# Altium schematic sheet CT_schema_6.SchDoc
size 274 x 160 mm
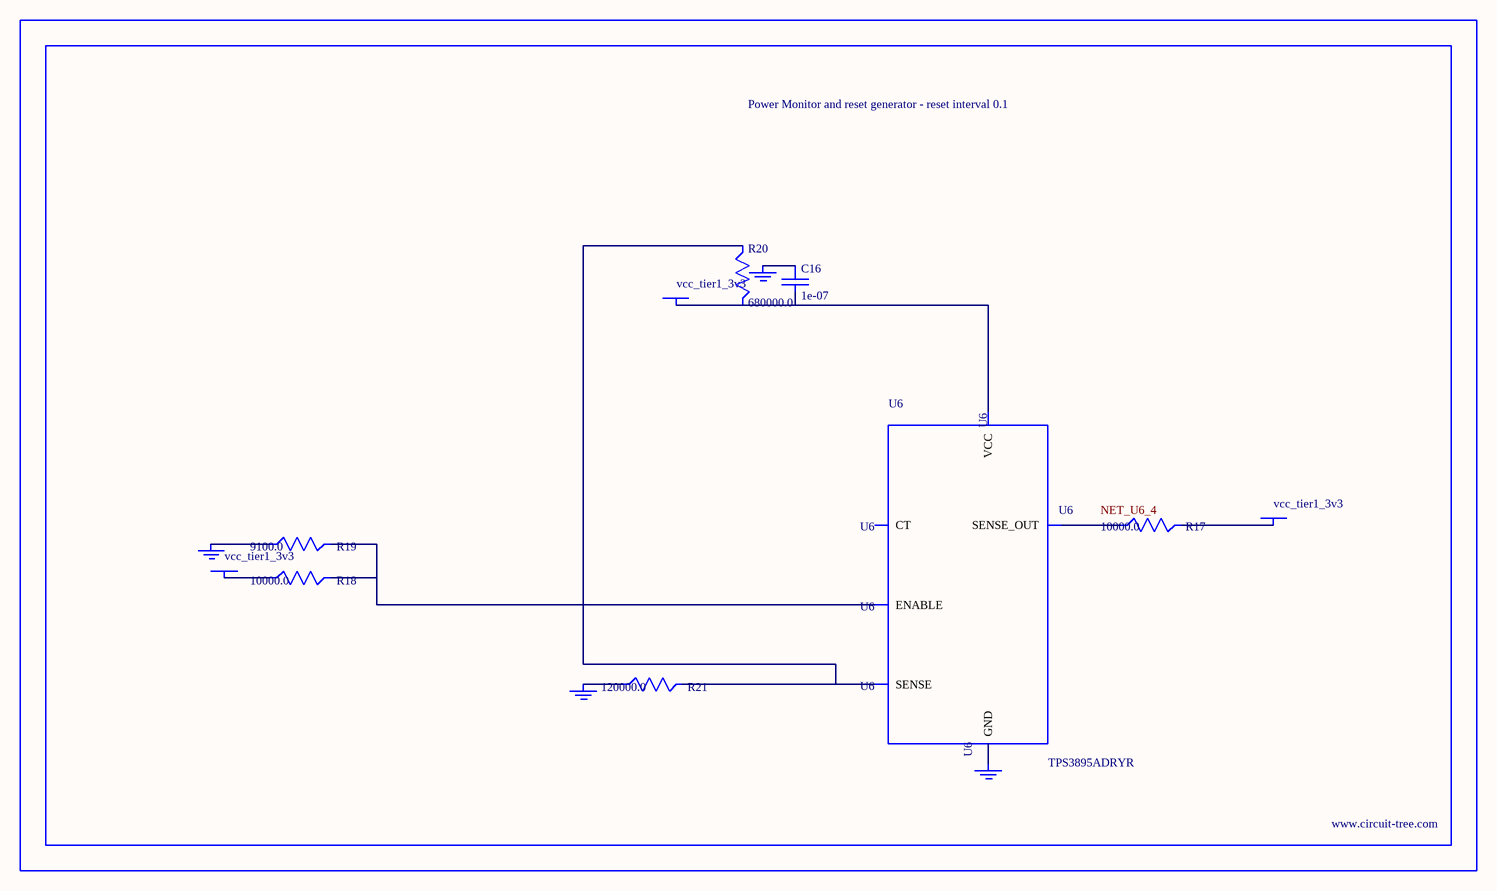
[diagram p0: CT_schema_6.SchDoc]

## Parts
BORDER5  (no value)
C16  1e-07  [C0402]
GND_INSTANCE_5_0  (no value)
GND_INSTANCE_5_1  (no value)
GND_INSTANCE_5_2  (no value)
GND_INSTANCE_5_3  (no value)
POWER_INSTANCE_5_0  vcc_tier1_3v3
POWER_INSTANCE_5_1  vcc_tier1_3v3
POWER_INSTANCE_5_2  vcc_tier1_3v3
R17  10000.0  [R0603]
R18  10000.0  [R0603]
R19  9100.0  [R0603]
R20  680000.0  [R0603]
R21  120000.0  [R0603]
U6  TPS3895ADRYR  [SON-6]

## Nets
NetC16_1: C16.1 GND_INSTANCE_5_2.0(GND)
NetC16_2: C16.2 POWER_INSTANCE_5_2.0(PWR) R20.2 U6.6(VCC)
NetGND_INSTANCE_5_0_0: GND_INSTANCE_5_0.0(GND) R19.1
NetGND_INSTANCE_5_1_0: GND_INSTANCE_5_1.0(GND) R21.1
NetGND_INSTANCE_5_3_0: GND_INSTANCE_5_3.0(GND) U6.2(GND)
NetPOWER_INSTANCE_5_0_0: POWER_INSTANCE_5_0.0(PWR) R18.1
NetPOWER_INSTANCE_5_1_0: POWER_INSTANCE_5_1.0(PWR) R17.2
NetR17_1: R17.1 U6.4(SENSE_OUT)
NetR18_2: R18.2 R19.2 U6.1(ENABLE)
NetR20_1: R20.1 R21.2 U6.3(SENSE)

Not connected (* = marked no-connect by the designer): U6 5(CT)

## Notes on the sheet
- Labels drawn without touching a wire or pin: NET_U6_4

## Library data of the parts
BORDER5 = BORDER_PAGE5
C16 = C0402C104K3RACTU
GND_INSTANCE_5_0-GND_INSTANCE_5_3 = GND
POWER_INSTANCE_5_0-POWER_INSTANCE_5_2 = PWR
R17 R18 = RC0603JR-0710KL
R19 = RC0603JR-079K1L
R20 = RC0603JR-07680KL
R21 = RC0603JR-07120KL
